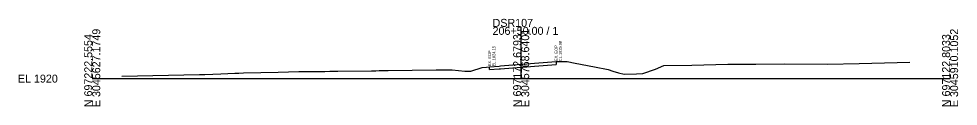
# Model space of a CAD drawing. Extents: x -26 to 19003, y -31 to 24541.
# Drawn here: x 1974.3 to 2302.8, y 12490.3 to 12521 of the extents above; entities that cross this region are included whole.
import ezdxf

# ---------------------------------------------------------------- set-up
doc = ezdxf.new("R2010")
doc.units = 0
for name, color, linetype in [('DESIGN - SHEET - Light Grid', 7, 'Continuous'), ('SURVEY - GROUND - Existing Pavement Layer', 7, 'Continuous'), ('SURVEY - GROUND - Existing Pavement Text', 7, 'Continuous'), ('SURVEY - GROUND - Top of Ground', 7, 'Continuous')]:
    doc.layers.add(name, color=color, linetype=linetype)

msp = doc.modelspace()

# ---------------------------------------------------------------- linework, layer by layer
at = {"layer": 'DESIGN - SHEET - Light Grid'}
for p, q in [((2150, 12500), (2150, 12518.15)), ((2000, 12500), (2150, 12500)), ((2150, 12500), (2300, 12500))]:
    msp.add_line(p, q, dxfattribs=at)
at = {"layer": 'SURVEY - GROUND - Existing Pavement Layer'}
for p, q in [((2138.97, 12503.15), (2138.97, 12504.15)), ((2142.75, 12503.46), (2150, 12504.02)), ((2150, 12504.02), (2150.63, 12504.07)), ((2150.63, 12504.07), (2154.68, 12504.38)), ((2154.68, 12504.38), (2162.21, 12504.98)), ((2162.21, 12505.98), (2162.21, 12504.98)), ((2138.97, 12503.15), (2142.25, 12503.41)), ((2142.25, 12503.41), (2142.75, 12503.46))]:
    msp.add_line(p, q, dxfattribs=at)
at = {"layer": 'SURVEY - GROUND - Top of Ground'}
msp.add_lwpolyline([(2010.3, 12500.89), (2037.53, 12501.43), (2039.39, 12501.47), (2044.97, 12501.7), (2049.88, 12501.91), (2051.24, 12501.95), (2052.94, 12502.01), (2064.96, 12502.28), (2072.27, 12502.53), (2080.42, 12502.51), (2081.28, 12502.53), (2083.12, 12502.56), (2085.93, 12502.6), (2097.64, 12502.76), (2099.19, 12502.78), (2100.29, 12502.79), (2103.47, 12502.87), (2120.32, 12503.13), (2122.32, 12503.1), (2125.92, 12503.13), (2130.3, 12502.67), (2130.85, 12502.56), (2131.17, 12502.56), (2132.38, 12502.6), (2136.41, 12503.88), (2137.9, 12504.04), (2138.97, 12504.15), (2142.25, 12504.41), (2142.75, 12504.46), (2150, 12505.02), (2150.63, 12505.07), (2154.68, 12505.38), (2162.21, 12505.98), (2162.88, 12506.03), (2163.32, 12506.05), (2165.08, 12506), (2166.08, 12505.99), (2168.89, 12505.39), (2175.62, 12504.15), (2180.45, 12503.22), (2182.07, 12502.66), (2184.02, 12502.07), (2185.97, 12501.52), (2190.35, 12501.69), (2192.56, 12501.83), (2197.02, 12503.34), (2199.94, 12504.6), (2209.63, 12504.74), (2222.27, 12505.01), (2232.01, 12505.1), (2242.2, 12505.17), (2257.1, 12505.1), (2268.25, 12505.31), (2285.95, 12505.72)], dxfattribs=at)

# ---------------------------------------------------------------- texts
at = {"layer": 'DESIGN - SHEET - Light Grid'}
for s, p in [('DSR107', (2140, 12518.15)), ('206+50.00 / 1', (2140, 12515.35)), ('EL 1920', (1974, 12498.6))]:
    msp.add_text(s, height=2.8, dxfattribs=at).set_placement(p)
for s, p in [('E 3045627.1749', (2002.8, 12490)), ('E 3045768.6401', (2152.8, 12490)), ('E 3045910.1052', (2302.8, 12490)), ('N 697222.5554', (2000, 12490)), ('N 697172.6793', (2150, 12490)), ('N 697122.8033', (2300, 12490))]:
    msp.add_text(s, height=2.8, rotation=90, dxfattribs=at).set_placement(p)
at = {"layer": 'SURVEY - GROUND - Existing Pavement Text'}
for s, p in [('EL.1924.15', (2140.97, 12504.35)), ('EX. EOP', (2162.71, 12506.18)), ('EL.1925.98', (2164.21, 12506.18)), ('EX. EOP', (2139.47, 12504.35))]:
    msp.add_text(s, height=1, rotation=90, dxfattribs=at).set_placement(p)

doc.saveas('drawing.dxf')
